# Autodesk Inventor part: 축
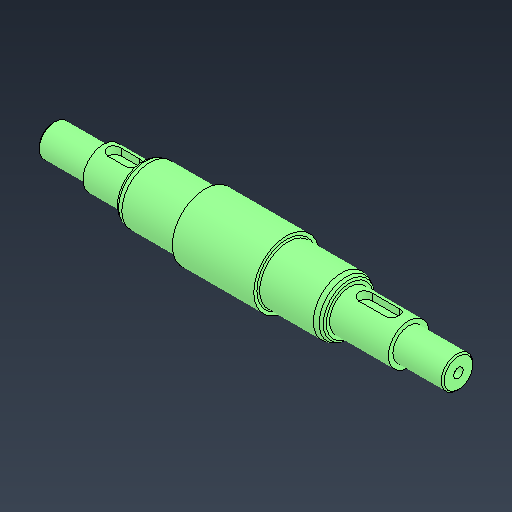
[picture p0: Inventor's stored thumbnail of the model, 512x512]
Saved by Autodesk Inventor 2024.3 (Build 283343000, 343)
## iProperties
Created: 2025-07
Part Number: 축
Material: 강철, 탄소
Document SubType Name: Modeling
Designer: user
Density: 7.85 g/cm^3
Appearance: 기본값
Author: jhkim
Sending System: Autodesk Inventor 2026
Preprocessor: ST-DEVELOPER v20.1
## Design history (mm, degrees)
feature "솔리드1"
node "솔리드2"
